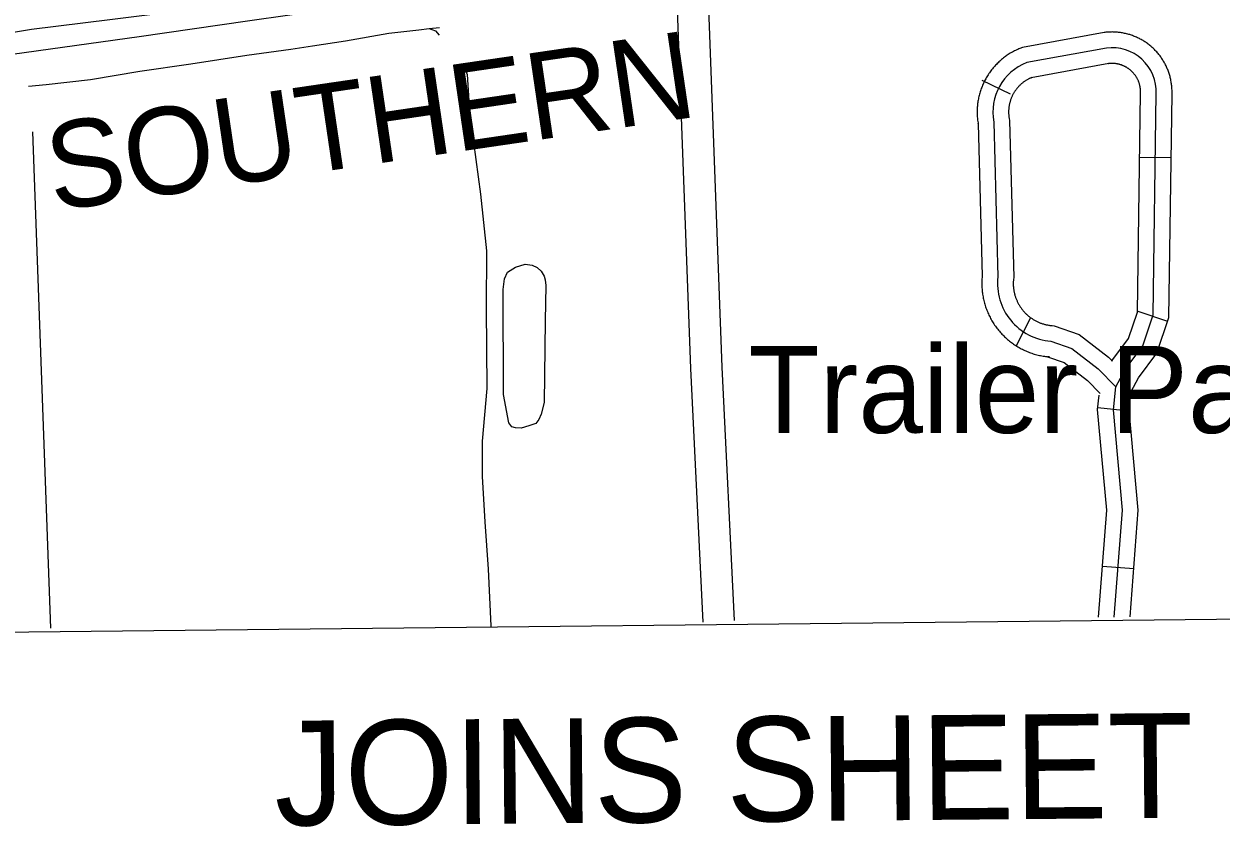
# Model space of a CAD drawing. Extents: x 3651524 to 3689615, y 505651 to 531377.
# Drawn here: x 3667884 to 3669026, y 511007 to 511774 of the extents above; entities that cross this region are included whole.
import ezdxf

# ---------------------------------------------------------------- set-up
doc = ezdxf.new("R2010")
doc.units = 0
for name, color, linetype in [('V-ANNO-TEXT', 7, 'Continuous'), ('V-GRID-FRAM', 7, 'Continuous'), ('V-RAIL-IDEN', 7, 'Continuous'), ('V-RAIL-TRAK', 7, 'Continuous'), ('V-ROAD-CNTR', 7, 'Continuous'), ('V-SITE-OTLN-IDEN', 7, 'Continuous'), ('V-SITE-VEGE', 7, 'Continuous'), ('V-TOPO-SHOR', 7, 'Continuous')]:
    doc.layers.add(name, color=color, linetype=linetype)

msp = doc.modelspace()

# ---------------------------------------------------------------- linework, layer by layer
at = {"layer": 'V-GRID-FRAM'}
msp.add_lwpolyline([(3655577.191, 529244.355), (3687244.414, 529585.207), (3687448.048, 511403.469), (3655764.959, 511062.446), (3655577.191, 529244.355)], dxfattribs=at)
at = {"layer": 'V-RAIL-TRAK'}
msp.add_lwpolyline([(3667872.442, 511744.82), (3667993.712, 511761.823), (3668096.958, 511776.779), (3668218.005, 511793.825), (3668297.707, 511805.556), (3668441.675, 511825.604)], dxfattribs=at)
at = {"layer": 'V-ROAD-CNTR'}
for p, q in [((3668824.922, 511706.527), (3668797.938, 511719.637)), ((3668948.142, 511646.599), (3668978.139, 511646.165)), ((3668843.884, 511493.085), (3668830.318, 511466.327)), ((3668946.382, 511499.587), (3668974.815, 511490.018)), ((3668908.234, 511407.459), (3668938.069, 511404.316)), ((3668912.619, 511255.943), (3668942.53, 511253.638))]:
    msp.add_line(p, q, dxfattribs=at)
for points in [[(3668481.846, 512565.582), (3668502.492, 511907.656), (3668519.64, 511444.566), (3668531.274, 511202.604)], [(3668511.832, 512566.522), (3668532.474, 511908.682), (3668549.614, 511445.842), (3668561.24, 511204.044)], [(3668920.901, 511765.992), (3668919.905, 511765.973), (3668918.851, 511765.927), (3668917.905, 511765.869), (3668916.915, 511765.798), (3668915.871, 511765.699), (3668914.928, 511765.592), (3668914.172, 511765.498), (3668836.275, 511751.238), (3668833.942, 511750.324), (3668832.857, 511749.87), (3668831.861, 511749.433), (3668830.815, 511748.96), (3668829.748, 511748.446), (3668828.774, 511747.958), (3668827.76, 511747.434), (3668826.718, 511746.865), (3668825.732, 511746.304), (3668824.744, 511745.719), (3668823.805, 511745.14), (3668822.85, 511744.536), (3668821.856, 511743.875), (3668820.913, 511743.223), (3668820.021, 511742.583), (3668819.104, 511741.908), (3668818.179, 511741.194), (3668817.285, 511740.483), (3668816.399, 511739.748), (3668815.554, 511739.025), (3668814.689, 511738.26), (3668813.831, 511737.47), (3668813.029, 511736.705), (3668812.211, 511735.905), (3668811.406, 511735.08), (3668810.619, 511734.252), (3668809.864, 511733.423), (3668809.087, 511732.55), (3668808.333, 511731.655), (3668807.641, 511730.814), (3668806.935, 511729.928), (3668806.228, 511729.006), (3668805.535, 511728.066), (3668804.896, 511727.164), (3668804.241, 511726.216), (3668803.589, 511725.222), (3668803.004, 511724.298), (3668802.419, 511723.346), (3668801.816, 511722.324), (3668801.262, 511721.333), (3668800.711, 511720.322), (3668800.198, 511719.323), (3668799.694, 511718.322), (3668799.187, 511717.249), (3668798.723, 511716.229), (3668798.276, 511715.196), (3668797.822, 511714.103), (3668797.417, 511713.056), (3668797.021, 511712.006), (3668796.641, 511710.92), (3668796.279, 511709.846), (3668795.926, 511708.72), (3668795.61, 511707.636), (3668795.318, 511706.584), (3668795.017, 511705.433), (3668794.754, 511704.308), (3668794.516, 511703.239), (3668794.283, 511702.095), (3668794.073, 511700.943), (3668793.89, 511699.83), (3668793.73, 511698.748), (3668793.573, 511697.589), (3668793.447, 511696.434), (3668793.338, 511695.309), (3668793.253, 511694.173), (3668793.182, 511693.029), (3668793.136, 511691.888), (3668793.106, 511690.771), (3668793.096, 511689.603), (3668793.109, 511688.446), (3668793.141, 511687.341), (3668793.189, 511686.193), (3668793.263, 511685.037), (3668793.355, 511683.883), (3668793.468, 511682.76), (3668793.591, 511681.67), (3668793.74, 511680.524), (3668793.919, 511679.337), (3668794.11, 511678.235), (3668794.065, 511678.481), (3668797.906, 511532.882), (3668797.894, 511532.77), (3668797.783, 511531.513), (3668797.7, 511530.338), (3668797.628, 511529.114), (3668797.582, 511527.849), (3668797.56, 511526.67), (3668797.551, 511525.445), (3668797.571, 511524.177), (3668797.612, 511522.954), (3668797.674, 511521.719), (3668797.755, 511520.54)], [(3668938.979, 511207.551), (3668946.837, 511309.526), (3668938.164, 511405.221), (3668940, 511422.644), (3668947.101, 511435.786), (3668964.529, 511459.455), (3668975.93, 511493.33), (3668979.016, 511706.799), (3668979.04, 511707.586), (3668979.048, 511708.616), (3668979.041, 511709.566), (3668979.02, 511710.571), (3668978.976, 511711.605), (3668978.919, 511712.551), (3668978.847, 511713.551), (3668978.748, 511714.595), (3668978.635, 511715.585), (3668978.506, 511716.576), (3668978.365, 511717.524), (3668978.207, 511718.509), (3668978.016, 511719.545), (3668977.817, 511720.524), (3668977.611, 511721.457), (3668977.383, 511722.431), (3668977.129, 511723.414), (3668976.865, 511724.38), (3668976.577, 511725.356), (3668976.287, 511726.282), (3668975.972, 511727.235), (3668975.631, 511728.203), (3668975.293, 511729.109), (3668974.927, 511730.052), (3668974.539, 511730.986), (3668974.151, 511731.89), (3668973.741, 511732.792), (3668973.305, 511733.72), (3668972.845, 511734.636), (3668972.406, 511735.485), (3668971.938, 511736.353), (3668971.44, 511737.242), (3668970.919, 511738.127), (3668970.417, 511738.946), (3668969.879, 511739.803), (3668969.303, 511740.671), (3668968.77, 511741.448), (3668968.2, 511742.258), (3668967.574, 511743.108), (3668966.976, 511743.885), (3668966.358, 511744.67), (3668965.728, 511745.432), (3668965.094, 511746.185), (3668964.401, 511746.968), (3668963.742, 511747.689), (3668963.073, 511748.398), (3668962.344, 511749.147), (3668961.638, 511749.836), (3668960.93, 511750.517), (3668960.192, 511751.193), (3668959.455, 511751.852), (3668958.661, 511752.533), (3668957.901, 511753.158), (3668957.157, 511753.754), (3668956.332, 511754.395), (3668955.52, 511754.993), (3668954.737, 511755.556), (3668953.896, 511756.137), (3668953.051, 511756.698), (3668952.215, 511757.232), (3668951.401, 511757.733), (3668950.518, 511758.262), (3668949.629, 511758.762), (3668948.763, 511759.238), (3668947.885, 511759.694), (3668946.99, 511760.147), (3668946.069, 511760.585), (3668945.192, 511760.988), (3668944.253, 511761.401), (3668943.315, 511761.789), (3668942.425, 511762.141), (3668941.479, 511762.501), (3668940.523, 511762.84), (3668939.562, 511763.164), (3668938.623, 511763.459), (3668937.706, 511763.736), (3668936.727, 511764.012), (3668935.701, 511764.28), (3668934.752, 511764.505), (3668933.812, 511764.718), (3668932.821, 511764.922), (3668931.85, 511765.106), (3668930.82, 511765.281), (3668929.838, 511765.426), (3668928.898, 511765.554), (3668927.854, 511765.677), (3668926.853, 511765.771), (3668925.921, 511765.849), (3668924.89, 511765.917), (3668923.883, 511765.961), (3668922.88, 511765.992), (3668921.84, 511766.001), (3668920.901, 511765.992)], [(3668916.447, 511750.665), (3668840.399, 511736.745)], [(3668921.327, 511735.995), (3668920.839, 511735.986), (3668920.419, 511735.968), (3668919.897, 511735.936), (3668919.411, 511735.901), (3668918.985, 511735.86), (3668918.466, 511735.801), (3668918.722, 511735.833), (3668844.523, 511722.251), (3668845.212, 511722.521), (3668844.679, 511722.297), (3668844.065, 511722.028), (3668843.501, 511721.773), (3668842.98, 511721.523), (3668842.388, 511721.225), (3668841.834, 511720.939), (3668841.33, 511720.664), (3668840.792, 511720.357), (3668840.258, 511720.042), (3668839.703, 511719.699), (3668839.172, 511719.363), (3668838.694, 511719.046), (3668838.195, 511718.7), (3668837.657, 511718.314), (3668837.158, 511717.947), (3668836.683, 511717.581), (3668836.205, 511717.2), (3668835.731, 511716.807), (3668835.242, 511716.388), (3668834.785, 511715.985), (3668834.351, 511715.585), (3668833.881, 511715.137), (3668833.443, 511714.707), (3668833.016, 511714.27), (3668832.587, 511713.818), (3668832.158, 511713.347), (3668831.765, 511712.906), (3668831.385, 511712.455), (3668830.957, 511711.936), (3668830.571, 511711.45), (3668830.206, 511710.976), (3668829.855, 511710.498), (3668829.472, 511709.958), (3668829.127, 511709.46), (3668828.813, 511708.98), (3668828.458, 511708.418), (3668828.119, 511707.868), (3668827.832, 511707.38), (3668827.522, 511706.827), (3668827.231, 511706.294), (3668826.942, 511705.729), (3668826.656, 511705.162), (3668826.407, 511704.635), (3668826.145, 511704.057), (3668825.894, 511703.48), (3668825.67, 511702.939), (3668825.441, 511702.348), (3668825.217, 511701.754), (3668825.015, 511701.178), (3668824.813, 511700.576), (3668824.642, 511700.03), (3668824.464, 511699.422), (3668824.286, 511698.78), (3668824.141, 511698.225), (3668824.004, 511697.638), (3668823.858, 511696.981), (3668823.739, 511696.401), (3668823.633, 511695.821), (3668823.532, 511695.204), (3668823.434, 511694.542), (3668823.355, 511693.957), (3668823.291, 511693.364), (3668823.23, 511692.737), (3668823.183, 511692.115), (3668823.144, 511691.497), (3668823.12, 511690.882), (3668823.102, 511690.241), (3668823.098, 511689.653), (3668823.105, 511689.044), (3668823.123, 511688.397), (3668823.149, 511687.779), (3668823.187, 511687.183), (3668823.235, 511686.575), (3668823.298, 511685.95), (3668823.373, 511685.29), (3668823.45, 511684.698), (3668823.535, 511684.137), (3668823.644, 511683.507), (3668823.993, 511681.607), (3668827.95, 511531.614), (3668827.748, 511529.802), (3668827.691, 511529.143), (3668827.638, 511528.396), (3668827.596, 511527.686), (3668827.572, 511527.023), (3668827.558, 511526.28), (3668827.553, 511525.569), (3668827.563, 511524.909), (3668827.586, 511524.21), (3668827.622, 511523.507), (3668827.673, 511522.768)], [(3668921.527, 511451.562), (3668921.703, 511451.888), (3668937.591, 511473.467), (3668946, 511498.454), (3668949.022, 511707.481), (3668949.044, 511708.174), (3668949.048, 511708.616), (3668949.043, 511709.14), (3668949.034, 511709.617), (3668949.014, 511710.057), (3668948.983, 511710.579), (3668948.949, 511711.055), (3668948.908, 511711.481), (3668948.855, 511711.953), (3668948.792, 511712.434), (3668948.717, 511712.942), (3668948.641, 511713.413), (3668948.564, 511713.833), (3668948.469, 511714.296), (3668948.357, 511714.805), (3668948.249, 511715.265), (3668948.133, 511715.718), (3668948.009, 511716.172), (3668947.877, 511716.616), (3668947.727, 511717.094), (3668947.578, 511717.547), (3668947.429, 511717.969), (3668947.251, 511718.445), (3668947.085, 511718.876), (3668946.905, 511719.308), (3668946.709, 511719.764), (3668946.509, 511720.204), (3668946.317, 511720.612), (3668946.115, 511721.016), (3668945.876, 511721.477), (3668945.646, 511721.905), (3668945.422, 511722.303), (3668945.195, 511722.69), (3668944.923, 511723.135), (3668944.677, 511723.526), (3668944.435, 511723.89), (3668944.134, 511724.329), (3668943.852, 511724.729), (3668943.608, 511725.061), (3668943.3, 511725.46), (3668943.006, 511725.835), (3668942.696, 511726.209), (3668942.382, 511726.582), (3668942.091, 511726.911), (3668941.758, 511727.276), (3668941.417, 511727.637), (3668941.11, 511727.952), (3668940.764, 511728.291), (3668940.408, 511728.632), (3668940.058, 511728.952), (3668939.689, 511729.283), (3668939.367, 511729.558), (3668938.985, 511729.873), (3668938.579, 511730.199), (3668938.236, 511730.464), (3668937.862, 511730.74), (3668937.441, 511731.043), (3668937.068, 511731.302), (3668936.683, 511731.557), (3668936.279, 511731.815), (3668935.835, 511732.088), (3668935.452, 511732.317), (3668935.055, 511732.541), (3668934.627, 511732.775), (3668934.193, 511733.001), (3668933.768, 511733.216), (3668933.357, 511733.412), (3668932.894, 511733.625), (3668932.485, 511733.804), (3668932.055, 511733.982), (3668931.577, 511734.172), (3668931.137, 511734.338), (3668930.707, 511734.491), (3668930.264, 511734.641), (3668929.797, 511734.788), (3668929.3, 511734.937), (3668928.863, 511735.061), (3668928.455, 511735.167), (3668927.97, 511735.282), (3668927.474, 511735.395), (3668927.013, 511735.489), (3668926.538, 511735.579), (3668926.112, 511735.652), (3668925.63, 511735.723), (3668925.112, 511735.793), (3668924.69, 511735.844), (3668924.215, 511735.888), (3668923.679, 511735.932), (3668923.242, 511735.962), (3668922.769, 511735.982), (3668922.292, 511735.997), (3668921.86, 511736), (3668921.327, 511735.995)], [(3668923.922, 511207.389), (3668931.785, 511309.425), (3668923.093, 511405.331), (3668925.393, 511427.166), (3668934.402, 511443.837), (3668951.06, 511466.461), (3668960.965, 511495.892), (3668964.019, 511707.14)], [(3668809.029, 511680.044), (3668812.928, 511532.248)], [(3667909.395, 511196.855), (3667892.1, 511670.795)], [(3668797.755, 511520.54), (3668797.852, 511519.335), (3668797.982, 511518.058), (3668798.132, 511516.829), (3668798.295, 511515.656), (3668798.48, 511514.444), (3668798.694, 511513.224), (3668798.922, 511512.016), (3668799.18, 511510.802), (3668799.443, 511509.645), (3668799.737, 511508.437), (3668800.059, 511507.227), (3668800.388, 511506.073), (3668800.742, 511504.893), (3668801.122, 511503.72), (3668801.515, 511502.565), (3668801.927, 511501.424), (3668802.37, 511500.25), (3668802.838, 511499.097), (3668803.295, 511498.009), (3668803.786, 511496.893), (3668804.31, 511495.757), (3668804.856, 511494.633), (3668805.395, 511493.573), (3668805.963, 511492.486), (3668806.583, 511491.366), (3668807.174, 511490.341), (3668807.787, 511489.307), (3668808.457, 511488.227), (3668809.122, 511487.203), (3668809.805, 511486.179), (3668810.497, 511485.192), (3668811.2, 511484.209), (3668811.965, 511483.19), (3668812.705, 511482.24), (3668813.459, 511481.3), (3668814.275, 511480.32), (3668815.064, 511479.415), (3668815.868, 511478.509), (3668816.715, 511477.6), (3668817.552, 511476.724), (3668818.442, 511475.83), (3668819.315, 511474.987), (3668820.173, 511474.179), (3668821.115, 511473.32), (3668822.053, 511472.506), (3668822.958, 511471.741), (3668823.919, 511470.955), (3668824.908, 511470.179), (3668825.879, 511469.447), (3668826.831, 511468.751), (3668827.847, 511468.029), (3668828.882, 511467.33), (3668829.901, 511466.662), (3668830.932, 511466.017), (3668831.994, 511465.369), (3668833.066, 511464.752), (3668834.099, 511464.174), (3668835.198, 511463.583), (3668836.308, 511463.016), (3668837.377, 511462.491), (3668838.498, 511461.96), (3668839.629, 511461.456), (3668840.766, 511460.968), (3668841.894, 511460.512), (3668843.006, 511460.079), (3668844.158, 511459.654), (3668845.367, 511459.232), (3668846.526, 511458.858), (3668847.657, 511458.506), (3668848.846, 511458.161), (3668850.02, 511457.841), (3668851.253, 511457.528), (3668852.44, 511457.257), (3668853.593, 511457.005), (3668854.839, 511456.757), (3668856.045, 511456.545), (3668857.214, 511456.354), (3668858.459, 511456.173), (3668859.672, 511456.024), (3668860.893, 511455.888), (3668862.102, 511455.782), (3668860.362, 511455.917), (3668876.114, 511450.479), (3668898.515, 511433.15), (3668910.447, 511420.983)], [(3668827.673, 511522.768), (3668827.73, 511522.051), (3668827.796, 511521.402), (3668827.88, 511520.721), (3668827.983, 511519.982), (3668828.088, 511519.29), (3668828.208, 511518.602), (3668828.338, 511517.92), (3668828.482, 511517.238), (3668828.645, 511516.521), (3668828.809, 511515.849), (3668828.983, 511515.197), (3668829.182, 511514.497), (3668829.382, 511513.833), (3668829.598, 511513.166), (3668829.827, 511512.489), (3668830.071, 511511.816), (3668830.308, 511511.186), (3668830.566, 511510.551), (3668830.857, 511509.859), (3668831.14, 511509.215), (3668831.424, 511508.599), (3668831.722, 511507.987), (3668832.061, 511507.319), (3668832.385, 511506.7), (3668832.701, 511506.128), (3668833.074, 511505.483), (3668833.445, 511504.855), (3668833.787, 511504.303), (3668834.178, 511503.701), (3668834.567, 511503.119), (3668834.981, 511502.528), (3668835.398, 511501.945), (3668835.797, 511501.414), (3668836.239, 511500.846), (3668836.689, 511500.286), (3668837.113, 511499.776), (3668837.59, 511499.229), (3668838.064, 511498.695), (3668838.533, 511498.192), (3668839.036, 511497.666), (3668839.5, 511497.198), (3668840.017, 511496.699), (3668840.563, 511496.185), (3668841.049, 511495.742), (3668841.567, 511495.294), (3668842.142, 511494.807), (3668842.673, 511494.373), (3668843.204, 511493.957), (3668843.767, 511493.531), (3668844.375, 511493.087), (3668844.931, 511492.691), (3668845.494, 511492.312), (3668846.089, 511491.922), (3668846.696, 511491.541), (3668847.286, 511491.183), (3668847.884, 511490.838), (3668848.533, 511490.474), (3668849.13, 511490.153), (3668849.742, 511489.84), (3668850.401, 511489.517), (3668851.03, 511489.22), (3668851.655, 511488.94), (3668852.3, 511488.664), (3668852.958, 511488.398), (3668853.644, 511488.131), (3668854.296, 511487.89), (3668854.915, 511487.674), (3668855.592, 511487.456), (3668856.297, 511487.236), (3668856.97, 511487.041), (3668857.652, 511486.855), (3668858.289, 511486.694), (3668858.988, 511486.533), (3668859.713, 511486.375), (3668860.361, 511486.247), (3668861.063, 511486.123), (3668861.794, 511486.004), (3668862.455, 511485.907), (3668863.162, 511485.82), (3668863.863, 511485.742), (3668864.572, 511485.68), (3668866.518, 511485.529), (3668890.568, 511477.227), (3668918.495, 511455.622), (3668922.243, 511451.8)], [(3668863.44, 511470.723), (3668883.341, 511463.853), (3668908.505, 511444.386), (3668925.393, 511427.166)], [(3668908.864, 511207.227), (3668916.733, 511309.324), (3668908.022, 511405.441), (3668909.49, 511419.383)]]:
    msp.add_lwpolyline(points, dxfattribs=at)
for centre, radius, start, end in [((3668921.757, 511708.709), 42.291, 357.873413, 97.212641), ((3668858.528, 511689.687), 50.429, 111.068656, 191.023954), ((3668867.836, 511525.829), 55.281, 173.332382, 265.439569)]:
    msp.add_arc(centre, radius, start, end, dxfattribs=at)
at = {"layer": 'V-SITE-VEGE'}
msp.add_lwpolyline([(3668365.225, 511389.941), (3668358.02, 511387.606), (3668352.612, 511388.108), (3668349.261, 511389.128), (3668346.163, 511392.984), (3668341.2, 511420.007), (3668340.948, 511520.173), (3668342.212, 511530.218), (3668345.028, 511536.664), (3668352.741, 511541.577), (3668361.746, 511544.174), (3668368.443, 511543.418), (3668373.342, 511541.112), (3668377.21, 511537.776), (3668380.057, 511532.889), (3668381.095, 511529.289), (3668381.624, 511523.882), (3668380.938, 511490.147), (3668379.844, 511412.381), (3668377.04, 511401.043), (3668374.994, 511395.886), (3668371.914, 511392.275)], close=True, dxfattribs=at)
at = {"layer": 'V-TOPO-SHOR'}
msp.add_line((3668270.303, 511769.411), (3668280, 511770.287), dxfattribs=at)
for points in [[(3667850.499, 511762.06), (3667890.937, 511768.624), (3667965.456, 511777.844), (3668006.176, 511783.026), (3668054.927, 511790.183), (3668123.613, 511801.871), (3668167.38, 511807.62), (3668203.394, 511811.671), (3668232.855, 511815.941), (3668262.672, 511820.262), (3668338.306, 511827.547), (3668386.779, 511835.26), (3668411.152, 511838.977)], [(3667887.886, 511714.356), (3667904.788, 511715.821), (3667947.173, 511720.732), (3667994.257, 511728.715), (3668043.007, 511735.596), (3668096.188, 511743.884), (3668138.293, 511749.625), (3668159.065, 511752.773), (3668190.365, 511757.63), (3668231.63, 511765.032), (3668260.444, 511767.938), (3668270.303, 511769.411)], [(3668270.303, 511769.411), (3668272.803, 511768.315), (3668276.412, 511767.221), (3668279.756, 511763.08)], [(3668304.019, 511731.873), (3668306.544, 511725.51), (3668307.445, 511710.545), (3668308.95, 511685.051), (3668312.67, 511660.676), (3668319.276, 511611.092), (3668325.074, 511557.068), (3668324.775, 511502.462), (3668325.138, 511425.682), (3668320.939, 511375.216), (3668320.819, 511341.675), (3668323.518, 511298.17), (3668326.502, 511253.001), (3668328.974, 511198.963), (3668329.062, 511197.681)]]:
    msp.add_lwpolyline(points, dxfattribs=at)

# ---------------------------------------------------------------- texts
at = {"layer": 'V-ANNO-TEXT'}
msp.add_text('JOINS SHEET 87', height=100, rotation=0.5, dxfattribs=at).set_placement((3668122.977, 511008.222))
at = {"layer": 'V-RAIL-IDEN'}
msp.add_text('SOUTHERN', height=82.9998, rotation=8.359225, dxfattribs=at).set_placement((3667911.623, 511594.893))
at = {"layer": 'V-SITE-OTLN-IDEN'}
msp.add_text('Trailer Park', height=82.99983, dxfattribs=at).set_placement((3668574.93, 511383.189))

doc.saveas('drawing.dxf')
